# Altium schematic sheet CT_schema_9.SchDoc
size 365 x 245 mm
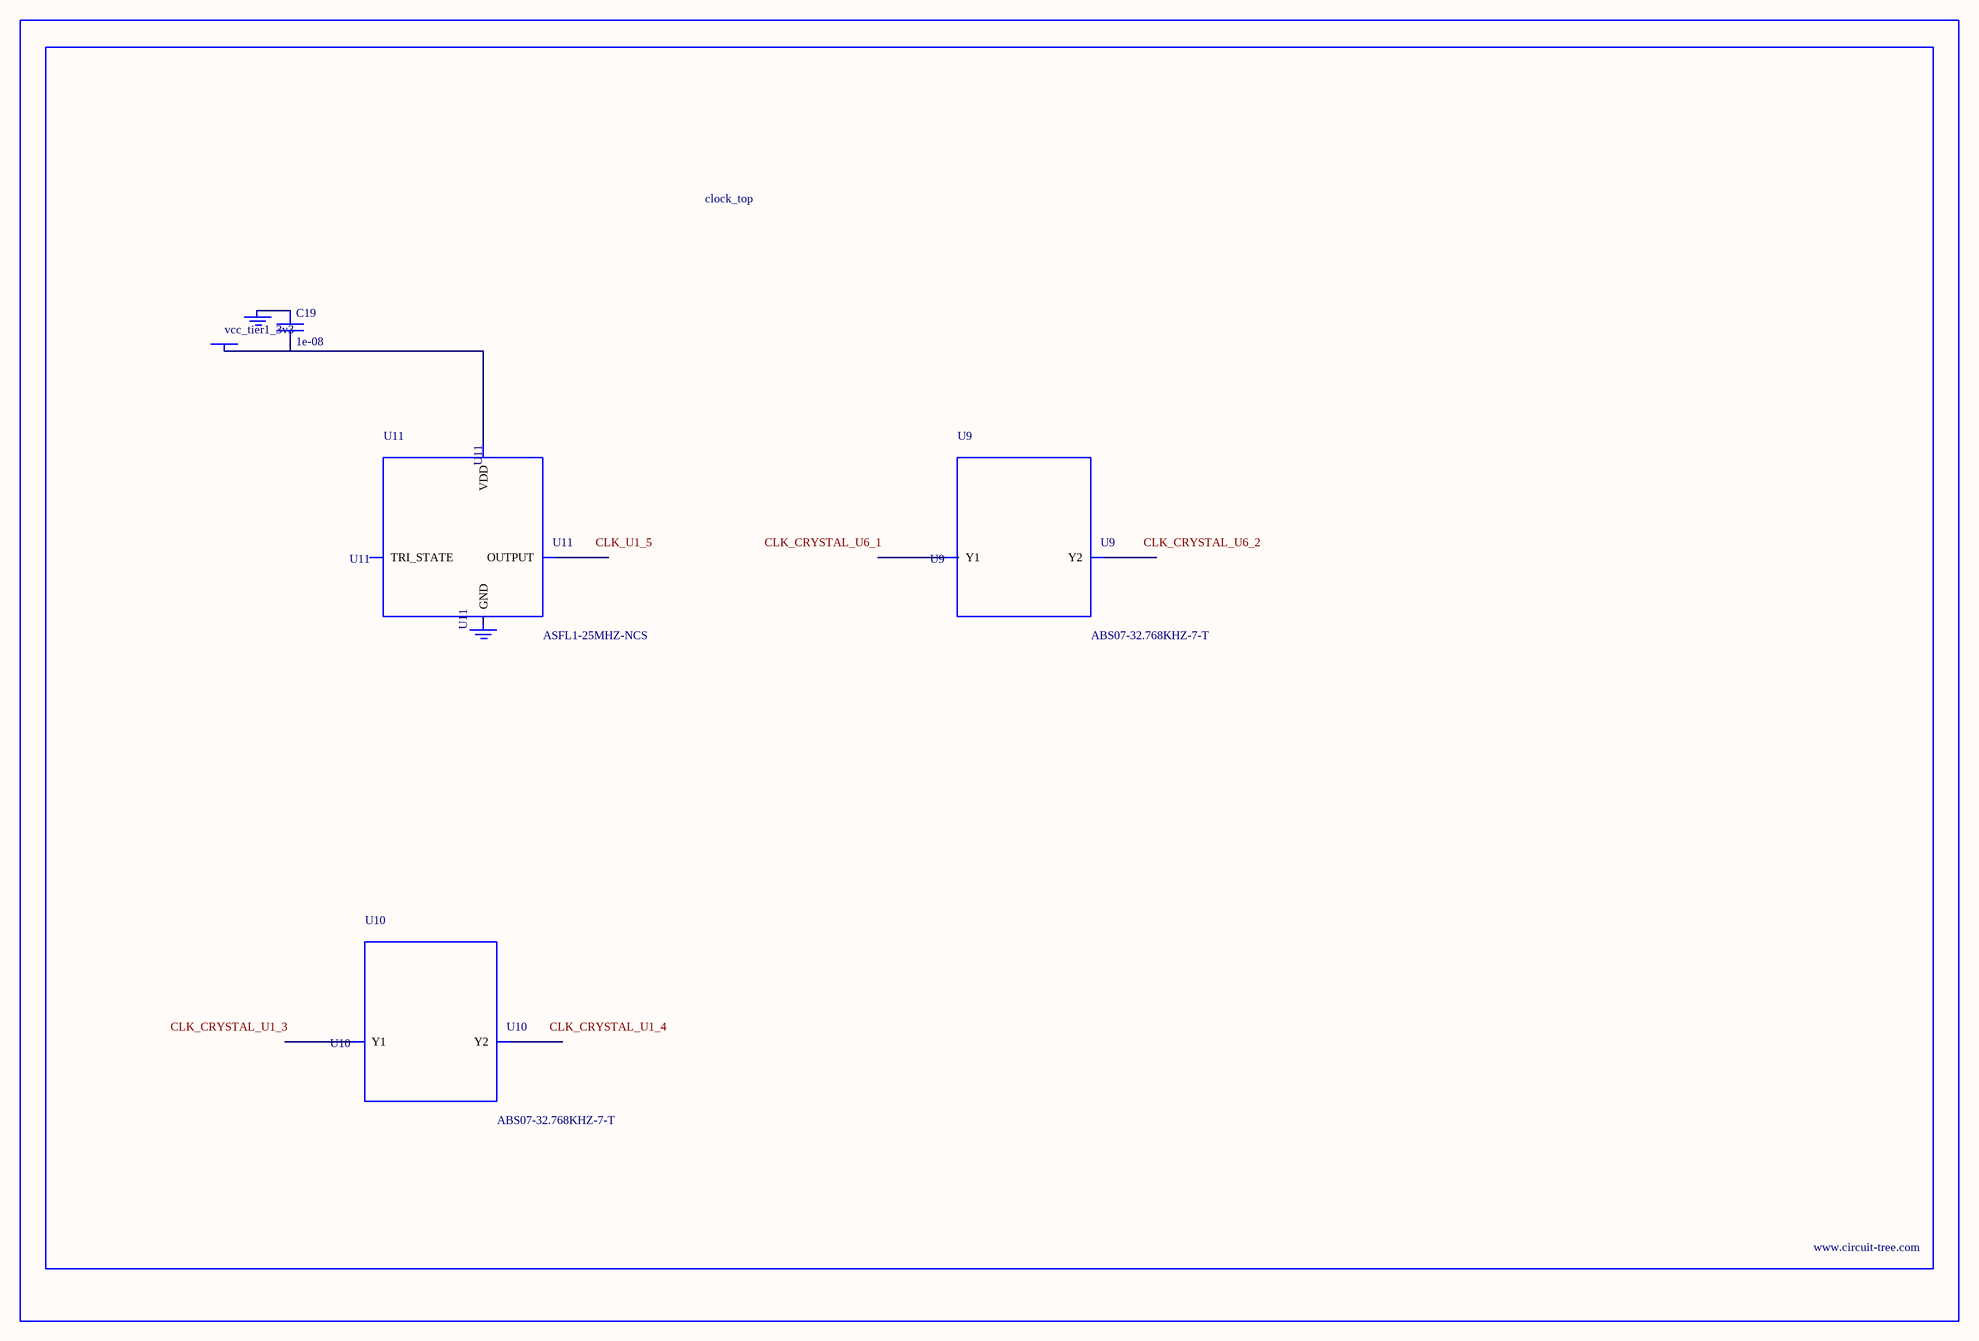
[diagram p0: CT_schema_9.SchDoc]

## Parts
BORDER8  (no value)
C19  1e-08  [C0402]
GND_INSTANCE_8_0  (no value)
GND_INSTANCE_8_1  (no value)
POWER_INSTANCE_8_0  vcc_tier1_3v3
U9  ABS07-32.768KHZ-7-T  [ABS07-32.768KHZ-7-T]
U10  ABS07-32.768KHZ-7-T  [ABS07-32.768KHZ-7-T]
U11  ASFL1-25MHZ-NCS  [ASFL1]

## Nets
NetC19_1: C19.1 GND_INSTANCE_8_0.0(GND)
NetC19_2: C19.2 POWER_INSTANCE_8_0.0(PWR) U11.4(VDD)

Not connected (* = marked no-connect by the designer): GND_INSTANCE_8_1 0(GND); U9 1(Y1) 2(Y2); U10 1(Y1) 2(Y2); U11 1(TRI_STATE) 2(GND) 3(OUTPUT)

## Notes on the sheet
- Labels drawn without touching a wire or pin: CLK_CRYSTAL_U1_3, CLK_CRYSTAL_U1_4, CLK_CRYSTAL_U6_1, CLK_CRYSTAL_U6_2, CLK_U1_5

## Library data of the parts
BORDER8 = BORDER_PAGE8
C19 = C0402C103K3RAC
GND_INSTANCE_8_0 GND_INSTANCE_8_1 = GND
POWER_INSTANCE_8_0 = PWR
